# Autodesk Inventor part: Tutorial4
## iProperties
Shininess: 64.0
Length Units: 11269
Angle Units: 11279
Time Units: 11290
Mass Units: 11283
Length Display Precision: 3
Angle Display Precision: 2
Compacted: True
Part Number: Tutorial4
Document SubType Name: Modeling
Created: 2003-10
Designer: Owner
Manufacturer: Standard
Standards Organization: Custom
Density: 0.0
Volumn: 0.0
Area: 0.0
PropertySet Name: Model Information
Control State: 0
Master: False
Checked Out: False
Author: Owner
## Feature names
1. Extrusion1
